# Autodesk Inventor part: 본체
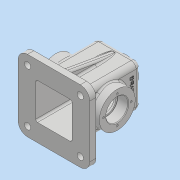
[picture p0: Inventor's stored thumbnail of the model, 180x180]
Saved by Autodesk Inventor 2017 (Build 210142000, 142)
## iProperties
Part Number: 본체
Material: 일반
Document SubType Name: Modeling
Designer: MRC
Density: 1 g/cm^3
Appearance: 기본값
Author: MRC
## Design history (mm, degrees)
sketch "스케치1"
  geometry: L1 (57, 57)-(-57, 57); L2 (-57, 57)-(-57, -57); L3 (-57, -57)-(57, -57); L4 (57, -57)-(57, 57); L5 (57, 57)-(-57, -57); L6 (-57, 57)-(57, -57); 1 further point
  constraints: 12 end point, 2 midpoint, 2 parallel, 1 horizontal, 1 perpendicular
  dimensions: "d0" = 114 distance of L3.end L2.end; "d1" = 114 distance of L2.end L1.end
extrude "돌출1" new body sketch "스케치1" distance "d2" = 10; taper "d3" = 0 deg
sketch "스케치2"
  geometry: L1 (-34, -34)-(34, -34); L2 (34, -34)-(34, 34); L3 (34, 34)-(-34, 34); L4 (-34, 34)-(-34, -34); L5 (-34, -34)-(34, 34); L6 (34, -34)-(-34, 34); 1 further point
  constraints: 12 end point, 2 midpoint, 2 parallel, 1 horizontal, 1 perpendicular
  dimensions: "d4" = 68 distance of L3.end L2.end; "d5" = 68 distance of L2.end L1.end
extrude "돌출2" join sketch "스케치2" distance "d6" = 95; taper "d7" = 0 deg
sketch "스케치3"
  geometry: L1 (-29, -29)-(29, -29); L2 (29, -29)-(29, 29); L3 (29, 29)-(-29, 29); L4 (-29, 29)-(-29, -29); L5 (-29, -29)-(29, 29); L6 (29, -29)-(-29, 29); 1 further point
  constraints: 12 end point, 2 midpoint, 2 parallel, 1 horizontal, 1 perpendicular
  dimensions: "d8" = 58 distance of L3.end L2.end; "d9" = 58 distance of L2.end L1.end
extrude "돌출3" cut sketch "스케치3" distance "d10" = 100; taper "d11" = 0 deg
node "작업 평면1"
sketch "스케치4"
  geometry: C1 r 20 at (0, 0); 1 further point
  constraints: 1 centre point, 1 coincident
  dimensions: "d13" = 40 diameter of C1
extrude "돌출4" join sketch "스케치4" stored distance "d14" = 100; taper "d15" = 8 deg
hole "구멍1" diameter "d18" = 22.835; stored, may be unused: countersink angle "d22" = 90 deg, drill point angle "d24" = 118 deg; dims "d16" = 10, "d17" = 10, "d19" = 50, "d20" = 4, "d21" = 2, "d23" = 59.3
sketch "스케치5"
  geometry: L1 (-23, -10)-(91, -10) reference; C1 r 28.5 at (34, 42); 2 further points
  constraints: 1 centre point, 1 midpoint, 1 vertical alignment
  dimensions: "d25" = 57 diameter of C1; "d26" = 52 distance from line of C1.centre L1
extrude "돌출5" join sketch "스케치5" distance "d27" = 15; taper "d28" = 0 deg
hole "구멍2" diameter "d31" = 30; stored, may be unused: countersink angle "d35" = 90 deg, drill point angle "d37" = 0 deg; dims "d29" = 10, "d30" = 10, "d32" = 50, "d33" = 35, "d34" = 17, "d36" = 30
sketch "스케치6"
  geometry: L1 (-57, -52)-(57, -52) reference; C1 r 15 at (0, 0) reference; 3 further points
  constraints: 1 midpoint, 1 vertical alignment
  dimensions: "d38" = 22 distance of point (0, 22) C1.centre
hole "구멍3" sketch "스케치6" at (0, 22) diameter "d39" = 3.242; stored, may be unused: countersink angle "d43" = 90 deg, drill point angle "d45" = 118 deg; dims "d40" = 8, "d41" = 35, "d42" = 17, "d44" = 10
sketch "스케치7"
  geometry: L1 (10, -57)-(10, 57) reference; L2 (10, 34)-(105, 34) reference; L3 (10, -34)-(105, -34) reference; L4 (10, 49)-(95.069, 34); L5 (10, -49)-(95.069, -34); L6 (0, 57)-(10, 57) reference; L7 (0, -57)-(10, -57) reference; 1 further point
  constraints: 4 end point, 4 point on line
  dimensions: "d49" = 10 deg angle of L4 L6; "d50" = 10 deg angle of L5 L7; "d51" = 8 distance from line of L4.start L6; "d52" = 8 distance from line of L5.start L7
feature "리브1" dims "d53" = 1, "d54" = 10, "d55" = 0, "d56" = 0, "d57" = 1, "d58" = 1
feature "리브2" dims "d59" = 1, "d60" = 10, "d61" = 0, "d62" = 0, "d63" = 1, "d64" = 1
fillet "모깎기1" dims "d65" = 15
sketch "스케치8"
  geometry: L1 (-57, -42)-(-57, 42) reference; L2 (-42, 57)-(42, 57) reference; L3 (57, 42)-(57, -42) reference; L4 (42, -57)-(-42, -57) reference; L5 (-5, -49)-(-5, -34) reference; L6 (-5, -34)-(-34, -34) reference; L7 (-34, -34)-(-34, 34) reference; L8 (-34, 34)-(-5, 34) reference; L9 (-5, 34)-(-5, 49) reference; L10 (-5, 49)-(5, 49) reference; L11 (5, 49)-(5, 34) reference; L12 (5, 34)-(34, 34) reference; L13 (34, 34)-(34, -34) reference; L14 (34, -34)-(5, -34) reference; L15 (5, -34)-(5, -49) reference; L16 (5, -49)-(-5, -49) reference; L17 (29, 29)-(-29, 29) reference; L18 (-29, 29)-(-29, -29) reference; L19 (-29, -29)-(29, -29) reference; L20 (29, -29)-(29, 29) reference; A1 r 15 centre (-42, -42) between (-57, -42) and (-42, -57) reference; A2 r 15 centre (-42, 42) between (-42, 57) and (-57, 42) reference; A3 r 15 centre (42, 42) between (57, 42) and (42, 57) reference; A4 r 15 centre (42, -42) between (42, -57) and (57, -42) reference; 5 further points
  constraints: 4 coincident
hole "구멍4" sketch "스케치8" at (42, -42), (-42, -42), (-42, 42), (42, 42) diameter "d66" = 10; stored, may be unused: countersink angle "d70" = 90 deg, drill point angle "d72" = 118 deg; dims "d67" = 8, "d68" = 18, "d69" = 2, "d71" = 10
sketch "스케치9"
  geometry: L1 (14, 105)-(54, 105) reference; L2 (0, 0)-(0, 95) reference; 2 further points
  constraints: 1 other
  dimensions: "d73" = 25 distance from line of L1 point (34, 80); "d74" = 34 distance from line of L2 point (34, 80)
feature "엠보싱1" sketch "스케치9" dims "d0" = 114, "d1" = 114, "d75" = 0.5, "d76" = 0
fillet "모깎기2" dims "d77" = 8
fillet "모깎기3" dims "d78" = 3
fillet "모깎기4" dims "d79" = 3
chamfer "모따기1" distance "d80" = 1; stored, may be unused: second distance "d81" = 2, angle "d82" = 45 deg
fillet "모깎기5" dims "d83" = 3
fillet "모깎기6" dims "d84" = 3
fillet "모깎기7" dims "d85" = 3
fillet "모깎기8" dims "d86" = 3
fillet "모깎기9" dims "d87" = 0.3
node "솔리드1"
pattern_circular "원형 패턴1" dims angle "d47" = 360 deg
mirror "미러1"
node "절단 모서리 투영1"
